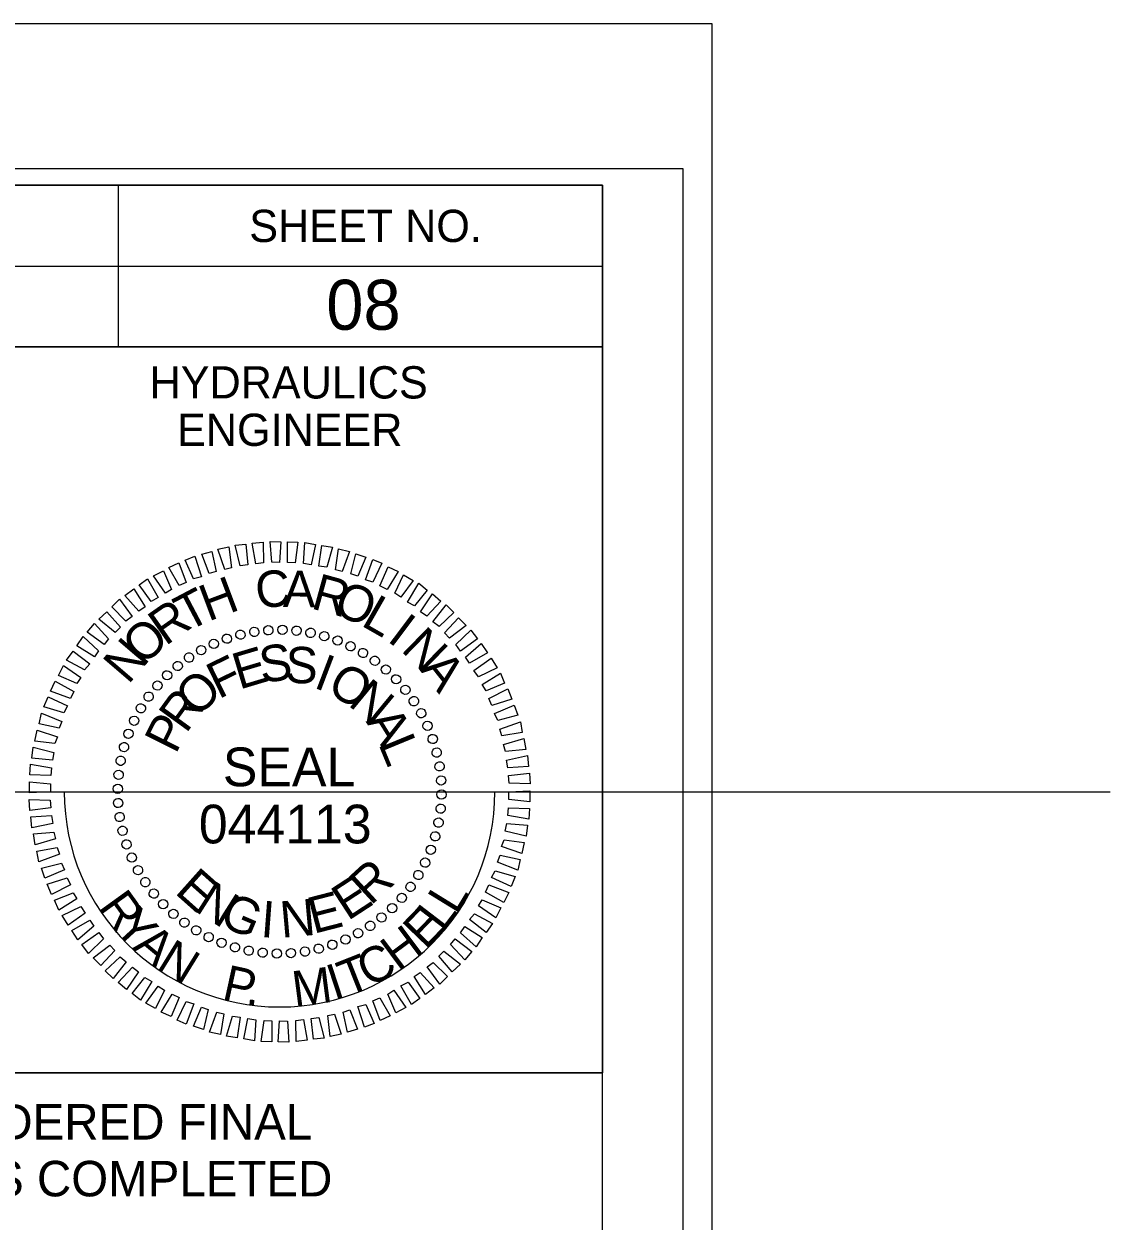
# Model space of a CAD drawing. Extents: x 1262239 to 1263984, y 747221 to 748321.
# Drawn here: x 1263816.1 to 1263984.4, y 748135.2 to 748320.7 of the extents above; entities that cross this region are included whole.
import ezdxf

# ---------------------------------------------------------------- set-up
doc = ezdxf.new("R2010")
doc.units = 0
for name, color, linetype in [('Prop Drainage Structure Bridge', 7, 'Continuous'), ('Prop Drainage Structure Bridge Opening', 7, 'Continuous'), ('Prop Grid Mask', 7, 'Continuous'), ('Prop Horizontal Alignment', 7, 'Continuous'), ('Prop Paved Shoulder', 7, 'Continuous'), ('Prop Terminator CELL', 7, 'Continuous'), ('Prop VPI Label', 7, 'Continuous'), ('Sheet Border Standard 30in CELL', 7, 'Continuous'), ('Sheet Layout Plan Border', 7, 'Continuous')]:
    doc.layers.add(name, color=color, linetype=linetype)

msp = doc.modelspace()

# ---------------------------------------------------------------- linework, layer by layer
at = {"layer": 'Prop Drainage Structure Bridge'}
for p, q in [((1263849.65, 748226.1), (1263849.65, 748226.1)), ((1263851.85, 748226.5), (1263851.85, 748226.5)), ((1263854, 748226.8), (1263854, 748226.8)), ((1263856.2, 748226.85), (1263856.2, 748226.85)), ((1263858.4, 748226.7), (1263858.4, 748226.7)), ((1263860.55, 748226.35), (1263860.55, 748226.35)), ((1263845.55, 748224.7), (1263845.55, 748224.7)), ((1263847.55, 748225.5), (1263847.55, 748225.5)), ((1263862.65, 748225.9), (1263862.65, 748225.9)), ((1263864.75, 748225.2), (1263864.75, 748225.2)), ((1263866.75, 748224.3), (1263866.75, 748224.3)), ((1263841.7, 748222.55), (1263841.7, 748222.55)), ((1263843.6, 748223.7), (1263843.6, 748223.7)), ((1263868.7, 748223.3), (1263868.7, 748223.3)), ((1263839.95, 748221.3), (1263839.95, 748221.3)), ((1263870.5, 748222.05), (1263870.5, 748222.05)), ((1263872.25, 748220.7), (1263872.25, 748220.7)), ((1263838.3, 748219.8), (1263838.3, 748219.8)), ((1263873.8, 748219.2), (1263873.8, 748219.2)), ((1263836.8, 748218.25), (1263836.8, 748218.25)), ((1263875.3, 748217.55), (1263875.3, 748217.55)), ((1263835.45, 748216.5), (1263835.45, 748216.5)), ((1263876.55, 748215.8), (1263876.55, 748215.8)), ((1263834.2, 748214.7), (1263834.2, 748214.7)), ((1263877.7, 748213.9), (1263877.7, 748213.9)), ((1263833.2, 748212.75), (1263833.2, 748212.75)), ((1263878.7, 748211.95), (1263878.7, 748211.95)), ((1263832.3, 748210.75), (1263832.3, 748210.75)), ((1263879.5, 748209.95), (1263879.5, 748209.95)), ((1263831.6, 748208.65), (1263831.6, 748208.65)), ((1263880.1, 748207.85), (1263880.1, 748207.85)), ((1263831.15, 748206.55), (1263831.15, 748206.55)), ((1263880.5, 748205.65), (1263880.5, 748205.65)), ((1263830.8, 748204.4), (1263830.8, 748204.4)), ((1263830.65, 748202.2), (1263830.65, 748202.2)), ((1263880.8, 748203.5), (1263880.8, 748203.5)), ((1263855.75, 748201.75), (1263855.75, 748201.75)), ((1263880.85, 748201.3), (1263880.85, 748201.3)), ((1263830.7, 748200), (1263830.7, 748200)), ((1263880.7, 748199.1), (1263880.7, 748199.1)), ((1263831, 748197.85), (1263831, 748197.85)), ((1263880.35, 748196.95), (1263880.35, 748196.95)), ((1263831.4, 748195.65), (1263831.4, 748195.65)), ((1263879.9, 748194.85), (1263879.9, 748194.85)), ((1263832, 748193.55), (1263832, 748193.55)), ((1263879.2, 748192.75), (1263879.2, 748192.75)), ((1263832.8, 748191.55), (1263832.8, 748191.55)), ((1263833.8, 748189.6), (1263833.8, 748189.6)), ((1263878.3, 748190.75), (1263878.3, 748190.75)), ((1263834.95, 748187.7), (1263834.95, 748187.7)), ((1263877.3, 748188.8), (1263877.3, 748188.8)), ((1263836.2, 748185.95), (1263836.2, 748185.95)), ((1263874.7, 748185.25), (1263874.7, 748185.25)), ((1263876.05, 748187), (1263876.05, 748187)), ((1263837.7, 748184.3), (1263837.7, 748184.3)), ((1263873.2, 748183.7), (1263873.2, 748183.7)), ((1263839.25, 748182.8), (1263839.25, 748182.8)), ((1263871.55, 748182.2), (1263871.55, 748182.2)), ((1263841, 748181.45), (1263841, 748181.45)), ((1263842.8, 748180.2), (1263842.8, 748180.2)), ((1263867.9, 748179.8), (1263867.9, 748179.8)), ((1263869.8, 748180.95), (1263869.8, 748180.95)), ((1263844.75, 748179.2), (1263844.75, 748179.2)), ((1263846.75, 748178.3), (1263846.75, 748178.3)), ((1263863.95, 748178), (1263863.95, 748178)), ((1263865.95, 748178.8), (1263865.95, 748178.8)), ((1263848.85, 748177.6), (1263848.85, 748177.6)), ((1263850.95, 748177.15), (1263850.95, 748177.15)), ((1263853.1, 748176.8), (1263853.1, 748176.8)), ((1263855.3, 748176.65), (1263855.3, 748176.65)), ((1263857.5, 748176.7), (1263857.5, 748176.7)), ((1263859.65, 748177), (1263859.65, 748177)), ((1263861.85, 748177.4), (1263861.85, 748177.4))]:
    msp.add_line(p, q, dxfattribs=at)
for points in [[(1263847.25, 748236.2), (1263846.2, 748239.35), (1263847.9, 748239.7), (1263848.3, 748236.45)], [(1263849.65, 748236.75), (1263848.85, 748239.95), (1263850.5, 748240.1), (1263850.85, 748236.9)], [(1263852.05, 748237.05), (1263851.5, 748240.25), (1263853.2, 748240.45), (1263853.25, 748237.2)], [(1263854.55, 748237.3), (1263854.3, 748240.55), (1263855.95, 748240.5), (1263855.75, 748237.25)], [(1263856.95, 748237.25), (1263856.95, 748240.5), (1263858.6, 748240.45), (1263858.15, 748237.2)], [(1263859.45, 748237.1), (1263859.65, 748240.35), (1263861.3, 748240.05), (1263860.65, 748236.9)], [(1263861.85, 748236.7), (1263862.3, 748239.9), (1263863.95, 748239.65), (1263863.05, 748236.55)], [(1263864.4, 748236.15), (1263864.9, 748239.4), (1263866.6, 748239), (1263865.45, 748235.9)], [(1263840.2, 748233.7), (1263838.6, 748236.5), (1263840.15, 748237.2), (1263841.3, 748234.15)], [(1263842.4, 748234.75), (1263841.1, 748237.65), (1263842.6, 748238.25), (1263843.65, 748235.05)], [(1263844.85, 748235.55), (1263843.7, 748238.55), (1263845.25, 748239), (1263845.9, 748235.9)], [(1263866.8, 748235.5), (1263867.55, 748238.6), (1263869.1, 748238.1), (1263867.85, 748235.15)], [(1263869.05, 748234.6), (1263870.2, 748237.75), (1263871.6, 748237.15), (1263870.2, 748234.25)], [(1263838.05, 748232.5), (1263836.2, 748235.2), (1263837.75, 748236), (1263839, 748233.1)], [(1263871.3, 748233.65), (1263872.55, 748236.6), (1263874.1, 748235.9), (1263872.4, 748233.1)], [(1263873.6, 748232.5), (1263874.95, 748235.35), (1263876.45, 748234.5), (1263874.55, 748231.9)], [(1263835.85, 748231.25), (1263834, 748233.8), (1263835.3, 748234.75), (1263836.95, 748231.85)], [(1263875.55, 748231.15), (1263877.3, 748234.05), (1263878.6, 748233), (1263876.65, 748230.55)], [(1263831.95, 748228.2), (1263829.75, 748230.4), (1263830.95, 748231.6), (1263832.9, 748228.9)], [(1263833.95, 748229.75), (1263831.8, 748232.15), (1263833.15, 748233.2), (1263834.9, 748230.4)], [(1263877.6, 748229.65), (1263879.45, 748232.4), (1263880.75, 748231.3), (1263878.55, 748228.95)], [(1263879.5, 748228.1), (1263881.55, 748230.7), (1263882.75, 748229.5), (1263880.45, 748227.35)], [(1263830.3, 748226.45), (1263827.75, 748228.5), (1263829, 748229.65), (1263831.1, 748227.25)], [(1263881.3, 748226.35), (1263883.45, 748228.7), (1263884.65, 748227.5), (1263882.05, 748225.55)], [(1263828.55, 748224.55), (1263825.95, 748226.5), (1263827.05, 748227.8), (1263829.25, 748225.45)], [(1263883.05, 748224.55), (1263885.35, 748226.8), (1263886.4, 748225.45), (1263883.75, 748223.55)], [(1263827.05, 748222.65), (1263824.35, 748224.35), (1263825.3, 748225.8), (1263827.7, 748223.6)], [(1263884.55, 748222.6), (1263887, 748224.7), (1263887.95, 748223.25), (1263885.15, 748221.65)], [(1263825.55, 748220.65), (1263822.75, 748222.15), (1263823.75, 748223.55), (1263826.35, 748221.55)], [(1263885.85, 748220.55), (1263888.5, 748222.45), (1263889.45, 748220.95), (1263886.55, 748219.55)], [(1263824.35, 748218.5), (1263821.5, 748219.75), (1263822.25, 748221.3), (1263824.95, 748219.45)], [(1263823.35, 748216.2), (1263820.25, 748217.35), (1263821, 748218.9), (1263823.85, 748217.3)], [(1263887.15, 748218.35), (1263889.95, 748220.1), (1263890.6, 748218.55), (1263887.75, 748217.4)], [(1263888.15, 748216.2), (1263891.1, 748217.7), (1263891.75, 748216.1), (1263888.65, 748215.1)], [(1263822.35, 748214), (1263819.25, 748214.9), (1263819.9, 748216.45), (1263822.9, 748215.05)], [(1263889.05, 748213.85), (1263892.1, 748215.15), (1263892.65, 748213.6), (1263889.55, 748212.8)], [(1263821.6, 748211.6), (1263818.5, 748212.25), (1263818.85, 748213.9), (1263822, 748212.65)], [(1263820.95, 748209.2), (1263817.85, 748209.6), (1263818.2, 748211.3), (1263821.35, 748210.25)], [(1263889.85, 748211.45), (1263893.05, 748212.6), (1263893.35, 748210.95), (1263890.2, 748210.4)], [(1263890.45, 748209.05), (1263893.6, 748210), (1263893.9, 748208.3), (1263890.75, 748208)], [(1263820.55, 748206.65), (1263817.35, 748206.95), (1263817.55, 748208.65), (1263820.8, 748207.85)], [(1263820.3, 748204.25), (1263817.05, 748204.35), (1263817.15, 748206), (1263820.4, 748205.45)], [(1263890.9, 748206.65), (1263894.15, 748207.35), (1263894.3, 748205.65), (1263891.1, 748205.45)], [(1263891.2, 748204.25), (1263894.45, 748204.65), (1263894.55, 748202.95), (1263891.3, 748203.05)], [(1263820.25, 748201.75), (1263817, 748201.6), (1263817, 748203.3), (1263820.25, 748202.95)], [(1263820.3, 748199.25), (1263817.05, 748198.85), (1263816.95, 748200.55), (1263820.2, 748200.45)], [(1263891.25, 748201.75), (1263894.5, 748201.9), (1263894.5, 748200.2), (1263891.25, 748200.55)], [(1263891.2, 748199.25), (1263894.45, 748199.15), (1263894.35, 748197.5), (1263891.1, 748198.05)], [(1263820.6, 748196.85), (1263817.35, 748196.15), (1263817.2, 748197.85), (1263820.4, 748198.05)], [(1263890.95, 748196.85), (1263894.15, 748196.55), (1263893.95, 748194.85), (1263890.7, 748195.65)], [(1263821.05, 748194.45), (1263817.9, 748193.5), (1263817.6, 748195.2), (1263820.75, 748195.5)], [(1263821.65, 748192.05), (1263818.45, 748190.9), (1263818.15, 748192.55), (1263821.3, 748193.1)], [(1263890.55, 748194.3), (1263893.65, 748193.9), (1263893.3, 748192.2), (1263890.15, 748193.25)], [(1263889.9, 748191.9), (1263893, 748191.25), (1263892.65, 748189.6), (1263889.5, 748190.85)], [(1263822.45, 748189.65), (1263819.4, 748188.35), (1263818.85, 748189.9), (1263821.95, 748190.7)], [(1263889.15, 748189.5), (1263892.25, 748188.6), (1263891.6, 748187.05), (1263888.6, 748188.45)], [(1263823.35, 748187.3), (1263820.4, 748185.8), (1263819.75, 748187.4), (1263822.85, 748188.4)], [(1263888.15, 748187.3), (1263891.25, 748186.15), (1263890.5, 748184.6), (1263887.65, 748186.2)], [(1263824.35, 748185.15), (1263821.55, 748183.4), (1263820.9, 748184.95), (1263823.75, 748186.1)], [(1263825.65, 748182.95), (1263823, 748181.05), (1263822.05, 748182.55), (1263824.95, 748183.95)], [(1263887.15, 748185), (1263890, 748183.75), (1263889.25, 748182.2), (1263886.55, 748184.05)], [(1263826.95, 748180.9), (1263824.5, 748178.8), (1263823.55, 748180.25), (1263826.35, 748181.85)], [(1263885.95, 748182.85), (1263888.75, 748181.35), (1263887.75, 748179.95), (1263885.15, 748181.95)], [(1263828.45, 748178.95), (1263826.15, 748176.7), (1263825.1, 748178.05), (1263827.75, 748179.95)], [(1263884.45, 748180.85), (1263887.15, 748179.15), (1263886.2, 748177.7), (1263883.8, 748179.9)], [(1263830.2, 748177.15), (1263828.05, 748174.8), (1263826.85, 748176), (1263829.45, 748177.95)], [(1263882.95, 748178.95), (1263885.55, 748177), (1263884.45, 748175.7), (1263882.25, 748178.05)], [(1263832, 748175.4), (1263829.95, 748172.8), (1263828.75, 748174), (1263831.05, 748176.15)], [(1263881.2, 748177.05), (1263883.75, 748175), (1263882.5, 748173.85), (1263880.4, 748176.25)], [(1263833.9, 748173.85), (1263832.05, 748171.1), (1263830.75, 748172.2), (1263832.95, 748174.55)], [(1263879.55, 748175.3), (1263881.75, 748173.1), (1263880.55, 748171.9), (1263878.6, 748174.6)], [(1263835.95, 748172.35), (1263834.2, 748169.45), (1263832.9, 748170.5), (1263834.85, 748172.95)], [(1263875.65, 748172.25), (1263877.5, 748169.7), (1263876.2, 748168.75), (1263874.55, 748171.65)], [(1263877.55, 748173.75), (1263879.7, 748171.35), (1263878.35, 748170.3), (1263876.6, 748173.1)], [(1263837.9, 748171), (1263836.55, 748168.15), (1263835.05, 748169), (1263836.95, 748171.6)], [(1263840.2, 748169.85), (1263838.95, 748166.9), (1263837.4, 748167.6), (1263839.1, 748170.4)], [(1263873.45, 748171), (1263875.3, 748168.3), (1263873.75, 748167.5), (1263872.5, 748170.4)], [(1263842.45, 748168.9), (1263841.3, 748165.75), (1263839.9, 748166.35), (1263841.3, 748169.25)], [(1263869.1, 748168.75), (1263870.4, 748165.85), (1263868.9, 748165.25), (1263867.85, 748168.45)], [(1263871.3, 748169.8), (1263872.9, 748167), (1263871.35, 748166.3), (1263870.2, 748169.35)], [(1263844.7, 748168), (1263843.95, 748164.9), (1263842.4, 748165.4), (1263843.65, 748168.35)], [(1263847.1, 748167.35), (1263846.6, 748164.1), (1263844.9, 748164.5), (1263846.05, 748167.6)], [(1263849.65, 748166.8), (1263849.2, 748163.6), (1263847.55, 748163.85), (1263848.45, 748166.95)], [(1263861.85, 748166.75), (1263862.65, 748163.55), (1263861, 748163.4), (1263860.65, 748166.6)], [(1263864.25, 748167.3), (1263865.3, 748164.15), (1263863.6, 748163.8), (1263863.2, 748167.05)], [(1263866.65, 748167.95), (1263867.8, 748164.95), (1263866.25, 748164.5), (1263865.6, 748167.6)], [(1263852.05, 748166.4), (1263851.85, 748163.15), (1263850.2, 748163.45), (1263850.85, 748166.6)], [(1263854.55, 748166.25), (1263854.55, 748163), (1263852.9, 748163.05), (1263853.35, 748166.3)], [(1263856.95, 748166.2), (1263857.2, 748162.95), (1263855.55, 748163), (1263855.75, 748166.25)], [(1263859.45, 748166.45), (1263860, 748163.25), (1263858.3, 748163.05), (1263858.25, 748166.3)]]:
    msp.add_lwpolyline(points, close=True, dxfattribs=at)
for centre, major_axis in [((1263847.59, 748225.47), (-0.234, 0.681)), ((1263849.69, 748226.09), (-0.174, 0.699)), ((1263851.83, 748226.52), (-0.113, 0.711)), ((1263854, 748226.77), (-0.05, 0.718)), ((1263856.19, 748226.83), (0.013, 0.72)), ((1263858.38, 748226.7), (0.075, 0.716)), ((1263860.54, 748226.37), (0.137, 0.707)), ((1263862.67, 748225.86), (0.198, 0.692)), ((1263843.6, 748223.69), (-0.349, 0.63)), ((1263845.55, 748224.66), (-0.293, 0.658)), ((1263864.74, 748225.17), (0.258, 0.672)), ((1263866.75, 748224.29), (0.316, 0.647)), ((1263841.73, 748222.55), (-0.403, 0.597)), ((1263868.67, 748223.25), (0.371, 0.617)), ((1263870.5, 748222.04), (0.423, 0.582)), ((1263838.33, 748219.79), (-0.5, 0.518)), ((1263839.97, 748221.24), (-0.453, 0.56)), ((1263872.21, 748220.68), (0.472, 0.543)), ((1263836.83, 748218.21), (-0.543, 0.472)), ((1263873.8, 748219.17), (0.518, 0.5)), ((1263835.46, 748216.49), (-0.582, 0.423)), ((1263875.24, 748217.54), (0.56, 0.453)), ((1263834.26, 748214.67), (-0.617, 0.371)), ((1263876.55, 748215.78), (0.597, 0.403)), ((1263833.21, 748212.75), (-0.647, 0.316)), ((1263877.69, 748213.91), (0.63, 0.349)), ((1263832.34, 748210.74), (-0.672, 0.258)), ((1263878.67, 748211.95), (0.658, 0.293)), ((1263831.65, 748208.67), (-0.692, 0.198)), ((1263879.47, 748209.92), (0.681, 0.234)), ((1263880.09, 748207.82), (0.699, 0.174)), ((1263831.13, 748206.54), (-0.707, 0.137)), ((1263880.53, 748205.68), (0.711, 0.113)), ((1263830.81, 748204.37), (-0.716, 0.075)), ((1263880.77, 748203.5), (0.718, 0.05)), ((1263830.68, 748202.19), (-0.72, 0.013)), ((1263880.83, 748201.32), (0.72, -0.013)), ((1263830.74, 748200), (-0.718, -0.05)), ((1263830.98, 748197.83), (-0.711, -0.113)), ((1263880.7, 748199.13), (0.716, -0.075)), ((1263831.42, 748195.69), (-0.699, -0.174)), ((1263880.37, 748196.97), (0.707, -0.137)), ((1263879.86, 748194.84), (0.692, -0.198)), ((1263832.04, 748193.59), (-0.681, -0.234)), ((1263879.17, 748192.76), (0.672, -0.258)), ((1263832.84, 748191.55), (-0.658, -0.293)), ((1263878.3, 748190.76), (0.647, -0.316)), ((1263833.82, 748189.59), (-0.63, -0.349)), ((1263877.25, 748188.84), (0.617, -0.371)), ((1263834.96, 748187.73), (-0.597, -0.403)), ((1263876.04, 748187.01), (0.582, -0.423)), ((1263836.26, 748185.97), (-0.56, -0.453)), ((1263874.68, 748185.3), (0.543, -0.472)), ((1263837.71, 748184.33), (-0.518, -0.5)), ((1263839.3, 748182.82), (-0.472, -0.543)), ((1263873.18, 748183.71), (0.5, -0.518)), ((1263841.01, 748181.46), (-0.423, -0.582)), ((1263869.78, 748180.96), (0.403, -0.597)), ((1263871.54, 748182.26), (0.453, -0.56)), ((1263842.84, 748180.26), (-0.371, -0.617)), ((1263844.76, 748179.21), (-0.316, -0.647)), ((1263865.96, 748178.84), (0.293, -0.658)), ((1263867.91, 748179.82), (0.349, -0.63)), ((1263846.77, 748178.34), (-0.258, -0.672)), ((1263848.84, 748177.64), (-0.198, -0.692)), ((1263850.97, 748177.13), (-0.137, -0.707)), ((1263861.82, 748177.42), (0.174, -0.699)), ((1263863.92, 748178.04), (0.234, -0.681)), ((1263853.13, 748176.81), (-0.075, -0.716)), ((1263855.32, 748176.68), (-0.013, -0.72)), ((1263857.5, 748176.73), (0.05, -0.718)), ((1263859.68, 748176.98), (0.113, -0.711))]:
    msp.add_ellipse(centre, major_axis=major_axis, ratio=0.999708, dxfattribs=at)
at = {"layer": 'Prop Drainage Structure Bridge Opening'}
msp.add_line((1263922.75, 748320.74), (1262238.75, 748320.74), dxfattribs=at)
at = {"layer": 'Prop Grid Mask'}
msp.add_line((1263755.7, 748201.75), (1263984.4, 748201.75), dxfattribs=at)
at = {"layer": 'Prop Horizontal Alignment'}
msp.add_arc((1263855.75, 748201.75), 33.36, 180, 360, dxfattribs=at)
at = {"layer": 'Prop Paved Shoulder'}
for p, q in [((1263830.75, 748295.69), (1263830.75, 748270.69)), ((1263705.7, 748283.19), (1263905.75, 748283.19))]:
    msp.add_line(p, q, dxfattribs=at)
for points in [[(1263905.75, 748295.74), (1262405.75, 748295.74), (1262405.75, 747245.74), (1263905.75, 747245.74)], [(1263705.7, 748295.74), (1263905.75, 748295.74), (1263905.75, 748270.69), (1263705.7, 748270.69)], [(1263805.75, 748270.69), (1263905.75, 748270.69), (1263905.75, 748158.19), (1263805.75, 748158.19)]]:
    msp.add_lwpolyline(points, close=True, dxfattribs=at)
at = {"layer": 'Prop Terminator CELL'}
msp.add_lwpolyline([(1263918.25, 748298.29), (1262251.75, 748298.29), (1262251.75, 747243.19), (1263918.25, 747243.19)], close=True, dxfattribs=at)
at = {"layer": 'Prop VPI Label'}
msp.add_lwpolyline([(1263922.75, 748320.74), (1262238.75, 748320.74), (1262238.75, 747220.74), (1263922.75, 747220.74)], close=True, dxfattribs=at)
at = {"layer": 'Sheet Layout Plan Border'}
for p, q in [((1263705.7, 748158.19), (1263905.74, 748158.19)), ((1263905.74, 748158.17), (1263905.74, 748134.67))]:
    msp.add_line(p, q, dxfattribs=at)

# ---------------------------------------------------------------- texts
at = {"layer": 'Prop Drainage Structure Bridge'}
for s, height, rotation, p in [('C', 5.64, 6.2199, (1263852.3, 748230.1)), ('A', 5.64, 359.0203, (1263856.25, 748230.4)), ('R', 5.64, 344.6211, (1263860.45, 748230.2)), ('T', 5.64, 27.8198, (1263841.45, 748226.45)), ('H', 5.64, 20.6195, (1263844.7, 748228.1)), ('O', 5.64, 337.4212, (1263863.8, 748229.45)), ('L', 5.64, 330.2209, (1263868.2, 748227.6)), ('R', 5.64, 35.0205, (1263838.05, 748224.25)), ('O', 5.64, 42.2217, (1263834.6, 748221.15)), ('I', 5.64, 323.0201, (1263872.25, 748225.2)), ('N', 5.64, 315.8189, (1263874.4, 748223.65)), ('N', 5.64, 49.4235, (1263832.3, 748218.25)), ('E', 5.64, 16.6111, (1263849.5, 748217.55)), ('S', 5.64, 7.2556, (1263852.95, 748218.6)), ('S', 5.64, 357.9004, (1263856.55, 748218.65)), ('F', 5.64, 25.967, (1263846.3, 748216.05)), ('I', 5.64, 339.1896, (1263860.85, 748217.95)), ('A', 5.64, 308.6172, (1263877.35, 748220.7)), ('O', 5.64, 329.8335, (1263862.85, 748217.25)), ('O', 5.64, 44.6812, (1263843, 748213.1)), ('N', 5.64, 320.4766, (1263866.2, 748215.25)), ('R', 5.64, 54.0397, (1263841.25, 748210.65)), ('P', 5.64, 63.3989, (1263839.65, 748207.45)), ('A', 5.64, 301.7603, (1263869.05, 748212.65)), ('L', 5.64, 292.4008, (1263871, 748209.2)), ('SEAL', 5.998, 360, (1263846.96, 748202.6)), ('044113', 5.998, 360, (1263843.24, 748193.74)), ('R', 5.64, 42.4814, (1263869.85, 748184)), ('E', 5.64, 318.2769, (1263839.35, 748186.1)), ('N', 5.64, 327.634, (1263842.35, 748183.4)), ('E', 5.64, 33.1241, (1263866.3, 748181.65)), ('R', 5.5, 305.8361, (1263827.53, 748183.85)), ('G', 5.64, 336.9902, (1263846.15, 748181.15)), ('E', 5.64, 14.4118, (1263861, 748179.7)), ('L', 5.5, 58.4194, (1263883.12, 748182.56)), ('Y', 5.5, 312.7625, (1263829.89, 748180.58)), ('I', 5.64, 355.7012, (1263852.7, 748179.25)), ('N', 5.64, 5.0564, (1263856.05, 748179.1)), ('E', 5.5, 46.0262, (1263878.36, 748177.14)), ('L', 5.5, 52.6092, (1263881.04, 748179.89)), ('A', 5.5, 320.0897, (1263832.8, 748177.45)), ('H', 5.5, 36.7814, (1263874.12, 748173.82)), ('N', 5.5, 328.2755, (1263836.49, 748174.43)), ('C', 5.5, 27.9087, (1263869.59, 748171.33)), ('T', 5.5, 21.6119, (1263866.17, 748169.99)), ('P', 5.5, 347.6523, (1263846.65, 748169.59)), ('M', 5.5, 7.4156, (1263858.06, 748168.41)), ('I', 5.5, 18.0915, (1263864.2, 748169.41)), ('.', 5.5, 354.2353, (1263850.4, 748168.76))]:
    msp.add_text(s, height=height, rotation=rotation, dxfattribs=at).set_placement(p)
at = {"layer": 'Prop Paved Shoulder'}
for s, p in [('SHEET NO.', (1263851.05, 748286.94)), ('HYDRAULICS', (1263835.61, 748262.69)), ('ENGINEER', (1263839.86, 748255.34))]:
    msp.add_text(s, height=5, dxfattribs=at).set_placement(p)
at = {"layer": 'Sheet Border Standard 30in CELL'}
msp.add_text('08', height=7.75, dxfattribs=at).set_placement((1263862.98, 748273.34))
at = {"layer": 'Sheet Layout Plan Border'}
for s, p in [('DOCUMENT NOT CONSIDERED FINAL', (1263726.78, 748147.84)), ('UNLESS ALL SIGNATURES COMPLETED', (1263721.7, 748139.04))]:
    msp.add_text(s, height=5.5, dxfattribs=at).set_placement(p)

doc.saveas('drawing.dxf')
